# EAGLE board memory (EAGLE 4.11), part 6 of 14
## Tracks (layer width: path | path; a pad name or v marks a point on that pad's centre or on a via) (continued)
-S  (via drill 0.61) (continued)
  Bottom 0.254: A23.H2 220.98,391.16 223.52,391.16 224.79,392.43 227.33,392.43 227.97,391.8 236.85,391.8 237.49,392.43 244.47,392.43 245.75,391.16 A21.H2 246.38,391.16 248.92,391.16 250.19,392.43 256.54,392.43 259.71,395.61 262.25,395.61 266.06,391.8 274.95,391.8 278.76,395.61 287.65,395.61 288.29,394.97 295.27,394.97 v295.27,393.7 | B40.K2 4.45,314.96 2.54,316.87 1.91,316.87 B40.J2 | 159.38,342.27 v158.75,342.9 | 159.38,342.27 219.07,342.27 v219.71,342.9 | v18.41,325.75 13.97,325.75 10.16,321.95 3.17,321.95 1.91,323.22 B40.F2 | v19.05,349.89 19.05,353.06 138.43,353.06 v139.06,352.43 | v141.6,342.9 142.24,342.27 159.38,342.27
-SA1  (via drill 0.61)
  Top 0.254: v347.35,285.12 346.71,284.48 v346.71,278.77 | v27.3,314.33 28.57,315.6 28.57,344.81 27.3,346.08 27.3,354.97 A38.V2
  Route2 0.254: v347.35,285.12 348.62,283.85 363.86,283.85 364.49,284.48 368.94,284.48 370.2,283.21 380.37,283.21 382.27,285.12 B10.V2 | v346.71,278.77 345.44,280.04 337.82,280.04 336.55,281.31 335.92,281.31 332.74,278.13 315.6,278.13 310.51,283.21 290.83,283.21 288.93,281.31 268.61,281.31 262.25,287.66 255.91,287.66 v245.75,297.81 | v175.9,306.07 172.09,309.88 161.29,309.88 160.66,309.25 151.76,309.25 147.96,313.06 142.24,313.06 141.6,312.42 135.89,312.42 132.08,316.23 125.09,316.23 121.28,312.42 110.49,312.42 106.68,316.23 97.79,316.23 97.16,315.6 94.61,315.6 91.44,318.77 85.09,318.77 84.45,319.41 75.56,319.41 68.58,312.42 59.69,312.42 59.05,313.06 51.44,313.06 46.35,307.98 45.09,307.98 40.64,312.42 34.29,312.42 33.66,313.06 28.57,313.06 v27.3,314.33
  Route3 0.254: v245.75,297.81 243.21,300.36 v243.21,300.99
  Bottom 0.254: A38.V2 27.3,356.24 29.21,358.14 29.84,358.14 A38.U2 | v243.21,300.99 245.75,303.53 245.75,306.07 237.49,306.07 236.85,306.71 227.97,306.71 227.33,306.07 224.79,306.07 224.16,306.71 215.26,306.71 214.63,306.07 212.09,306.07 211.46,306.71 202.56,306.71 201.93,306.07 199.39,306.07 198.75,306.71 189.87,306.71 189.23,306.07 186.69,306.07 186.06,306.71 177.16,306.71 176.53,306.07 v175.9,306.07
-SAC  (via drill 0.61)
  Top 0.254: 260.35,393.06 255.91,393.06 A20.F2 | 260.35,393.06 260.35,379.73 259.08,378.46 A20.M2 | v264.8,400.05 260.35,395.61 260.35,393.06
  Route2 0.254: v426.72,419.1 425.45,417.83 306.7,417.83 v304.8,415.93
  Route3 0.254: v503.56,261.62 504.82,262.89 504.82,363.22 448.94,419.1 v426.72,419.1 | v280.67,415.93 v264.8,400.05
  Bottom 0.254: v503.56,261.62 501.01,259.08 500.38,259.08 500.38,255.91 504.82,251.46 504.82,186.69 497.84,179.7 497.2,179.7 497.2,175.26 D01.L2 | v304.8,415.93 304.17,416.56 281.31,416.56 v280.67,415.93
-SAC00  (via drill 0.61)
  Top 0.254: v411.48,73.66 411.48,85.09 E08.U2 | v501.65,109.22 501.65,115.57 500.38,116.84 E01.H2
  Bottom 0.254: v411.48,73.66 412.12,73.02 475.62,73.02 476.25,72.39 494.67,72.39 | 494.67,72.39 497.84,69.22 497.84,64.77 494.03,64.77 485.14,55.88 480.06,55.88 473.71,49.53 466.09,49.53 465.45,48.9 464.19,48.9 462.92,50.16 459.11,50.16 F04.F2 | v501.65,109.22 501.65,72.39 494.67,72.39
-SAC01  (via drill 0.61)
  Top 0.254: v493.39,32.38 498.48,37.46 498.48,69.22 | 498.48,69.22 498.48,121.92 499.75,123.19 E01.E2 | v413.38,70.48 410.21,73.66 410.21,81.28 407.04,81.28 406.4,81.91 406.4,83.18 407.04,83.82 407.04,87.63 407.67,88.27 E08.T2 | 498.48,69.22 v496.57,69.22
  Bottom 0.254: v493.39,32.38 490.86,29.84 490.22,29.84 489.58,30.48 480.69,30.48 474.35,24.13 468,24.13 467.36,23.49 460.38,23.49 459.11,24.77 F04.R2 | v413.38,70.48 422.27,70.48 422.91,71.12 487.05,71.12 488.95,69.22 v496.57,69.22
-SAC02  (via drill 0.61)
  Top 0.254: v442.6,93.98 444.5,95.88 444.5,108.58 v446.4,110.49 | v459.11,147.32 458.47,146.69 458.47,135.25 457.2,133.99 457.2,122.55 458.47,121.28 E04.F2
  Bottom 0.254: v442.6,93.98 441.96,93.34 439.42,93.34 438.79,93.98 429.89,93.98 429.26,93.34 426.72,93.34 426.08,93.98 417.19,93.98 416.56,93.34 412.12,93.34 411.48,92.71 E08.S2 | v446.4,110.49 455.93,120.02 458.47,120.02 E04.F2 | v459.11,147.32 499.75,147.32 499.75,151.76 D01.U2
-SAC03
  Route2 0.254: D01.P2 499.75,164.47 499.75,160.02 499.11,160.02 495.3,156.21 495.3,138.43 493.39,138.43 460.38,105.41 460.38,95.88 459.11,95.88 E04.R2
  Bottom 0.254: E08.R2 408.31,95.25 412.12,95.25 414.02,97.16 416.56,97.16 417.19,96.52 426.08,96.52 426.72,97.16 429.26,97.16 429.89,96.52 438.79,96.52 442.6,100.33 451.49,100.33 455.93,95.88 458.47,95.88 E04.R2
-SAC04  (via drill 0.61)
  Top 0.254: v415.93,98.42 415.93,126.36 419.1,129.54 v419.1,145.41 | v441.32,145.41 v441.32,186.06
  Route2 0.254: v494.03,187.32 495.3,186.06 496.57,186.06 496.57,181.61 D01.J2
  Bottom 0.254: v415.93,98.42 411.48,98.42 E08.P2 | v419.1,145.41 v441.32,145.41 | v441.32,186.06 450.21,186.06 450.85,185.42 454.66,185.42 455.93,186.69 458.47,186.69 D04.F2 459.11,187.96 460.38,189.23 465.45,189.23 466.09,188.59 468.63,188.59 469.26,189.23 478.15,189.23 478.79,188.59 481.33,188.59 481.96,189.23 492.12,189.23 v494.03,187.32
-SAC05  (via drill 0.61)
  Top 0.254: v406.4,140.34 406.4,107.31 407.04,106.68 407.04,102.87 407.67,102.23 E08.N2 | v457.2,141.6 457.2,160.02 458.47,161.29 D04.R2 | v499.75,168.91 501.65,170.81 501.65,184.78 500.38,186.06 500.38,189.86 D01.E2
  Bottom 0.254: v406.4,140.34 407.04,140.97 410.85,140.97 411.48,140.34 427.36,140.34 428.62,141.6 v457.2,141.6 | v499.75,168.91 487.68,156.84 480.06,156.84 476.88,160.02 469.26,160.02 465.45,163.83 460.38,163.83 459.11,162.56 D04.R2
-SAC06  (via drill 0.61)
  Top 0.254: v487.68,140.34 487.68,150.5 488.95,151.76 488.95,204.47 493.39,208.91 v493.39,217.17 | v477.52,254 479.43,252.09 v479.43,224.79
  Route2 0.254: v477.52,128.91 487.68,139.06 v487.68,140.34
  Bottom 0.254: v477.52,128.91 474.35,125.73 468,125.73 466.09,123.82 465.45,123.82 463.55,125.73 455.3,125.73 448.31,118.74 444.5,118.74 438.15,125.09 434.34,125.09 427.99,118.74 422.91,118.74 414.02,109.85 411.48,109.85 411.48,105.41 E08.M2 | v493.39,217.17 493.39,220.34 | 493.39,220.34 495.3,220.34 497.2,222.25 499.75,222.25 C01.U2 | v477.52,254 475.62,255.91 468,255.91 467.36,255.27 460.38,255.27 459.11,256.54 C04.F2 | v479.43,224.79 480.06,224.16 485.14,224.16 485.77,223.52 490.22,223.52 493.39,220.34
-SAC07  (via drill 0.61)
  Top 0.254: v409.57,139.7 409.57,119.38 410.85,118.11 E08.H2 | v428.62,140.34 428.62,179.7 431.8,182.88 v431.8,203.2 | v454.02,204.47 v454.02,231.14
  Bottom 0.254: v409.57,139.7 427.99,139.7 v428.62,140.34 | v431.8,203.2 433.07,204.47 441.96,204.47 442.6,205.1 453.39,205.1 v454.02,204.47 | v454.02,231.14 458.47,231.14 C04.R2 459.11,231.78 461.01,231.78 462.92,233.68 465.45,233.68 469.26,229.87 478.15,229.87 478.79,230.5 481.33,230.5 481.96,229.87 490.86,229.87 491.49,230.5 498.48,230.5 499.75,229.23 C01.S2
-SAC08  (via drill 0.61)
  Top 0.254: v452.12,123.82 454.02,125.73 454.02,135.89 v452.75,137.16 | v497.84,137.79 498.48,138.43 498.48,236.22 | 498.48,236.22 497.2,237.49 C01.N2 | v486.41,312.42 488.95,309.88 488.95,302.26 498.48,292.74 498.48,236.22
  Route2 0.254: v471.81,321.31 480.69,312.42 v486.41,312.42
  Bottom 0.254: v452.12,123.82 447.68,119.38 445.13,119.38 438.79,125.73 428.62,125.73 415.29,112.39 412.12,112.39 411.48,111.76 E08.K2 | v452.75,137.16 455.3,139.7 455.93,139.06 486.41,139.06 487.05,138.43 497.2,138.43 v497.84,137.79 | v471.81,321.31 471.17,321.31 469.26,323.22 467.36,323.22 466.09,321.95 460.38,321.95 459.11,323.22 B04.F2
-SAC09  (via drill 0.61)
  Top 0.254: v492.12,141.6 492.12,206.38 494.67,208.91 494.67,220.98 495.3,221.61 495.3,245.75 496.57,247.01 496.57,250.19 C01.J2 | v486.41,299.72 492.12,294 v492.12,252.09
  Route3 0.254: v411.48,141.6 411.48,140.34 409.57,138.43 409.57,122.55 408.31,121.28 E08.F2
  Bottom 0.254: v411.48,141.6 427.36,141.6 427.99,142.24 456.56,142.24 457.2,142.88 459.11,140.97 487.05,140.97 487.68,141.6 v492.12,141.6 | v486.41,299.72 480.69,299.72 480.06,300.36 477.52,300.36 476.88,299.72 468,299.72 467.36,300.36 464.82,300.36 464.19,299.72 459.74,299.72 459.11,299.09 B04.R2 | v492.12,252.09 492.76,251.46 496.57,251.46 C01.J2
-SAC10  (via drill 0.61)
  Top 0.254: v490.86,241.3 494.67,245.11 494.67,246.38 495.3,247.01 495.3,252.09 496.57,253.36 v496.57,254.63 | v492.76,361.95 504.82,349.89 504.82,297.81 502.29,295.28 502.29,293.37 501.65,292.74 v501.65,281.31
  Route2 0.254: v492.76,361.95 465.45,389.25 459.11,389.25 459.11,393.06 A04.F2
  Route3 0.254: v421,212.72 419.1,210.82 419.1,183.51 415.93,180.34 415.93,143.51 412.75,140.34 412.75,125.73 411.48,124.46 E08.E2 | v490.86,220.98 492.12,222.25 492.12,240.03 v490.86,241.3
  Bottom 0.254: v421,212.72 422.27,214 447.04,214 447.68,213.36 450.85,213.36 452.12,214.63 476.25,214.63 479.43,217.81 480.69,217.81 483.87,220.98 v490.86,220.98 | v496.57,254.63 499.75,257.81 499.75,259.72 C01.E2 500.38,260.99 501.65,260.99 501.65,270.51 502.92,271.78 502.92,277.5 501.65,278.77 v501.65,281.31
-SAC11  (via drill 0.61)
  Top 0.254: v408.31,131.44 408.31,127.63 E08.D2 | v499.75,139.06 501.65,140.97 501.65,169.54 504.82,172.72 504.82,276.86 500.38,281.31 500.38,288.29 B01.U2 500.38,289.56 500.38,292.74 501.65,294 501.65,348.62 v490.22,360.05
  Route2 0.254: v408.31,131.44 418.46,141.6 428.62,141.6 v429.89,140.34 | v490.22,360.05 483.87,360.05 476.88,367.03 468,367.03 467.36,366.4 460.38,366.4 459.11,367.67 A04.R2
  Bottom 0.254: v429.89,140.34 431.17,139.06 436.88,139.06 438.15,140.34 455.93,140.34 456.56,139.7 487.05,139.7 487.68,139.06 v499.75,139.06
-SIK  (via drill 0.61)
  Top 0.254: v275.59,409.58 282.57,416.56 300.99,416.56 300.99,414.02 v306.7,408.31 | v312.42,410.21 314.32,412.12 314.32,419.74 316.23,421.64 495.3,421.64 495.3,395.61 496.57,394.34 A01.F2
  Route2 0.254: v122.56,390.53 127.64,395.61 137.16,395.61 140.97,391.8 149.86,391.8 153.67,395.61 162.56,395.61 163.19,394.97 172.09,394.97 175.9,398.78 180.34,398.78 180.97,398.15 186.69,398.15 193.04,404.5 200.66,404.5 208.28,412.12 246.38,412.12 254,404.5 264.16,404.5 267.97,408.31 274.32,408.31 v275.59,409.58 | v306.7,408.31 310.51,408.31 v312.42,410.21
  Route3 0.254: v90.17,307.98 85.72,312.42 85.72,346.71 95.25,356.24 95.25,368.94 115.57,389.25 122.56,389.25 v122.56,390.53
  Bottom 0.254: v90.17,307.98 93.34,307.98 B33.M2
-SL  (via drill 0.61)
  Top 0.254: v481.33,270.51 478.79,273.05 478.79,284.48 479.43,285.12 v479.43,292.1 | v494.03,298.45 498.48,302.9 v498.48,350.52
  Route2 0.254: v485.77,255.27 485.77,268.61 483.24,268.61 v481.33,270.51 | v498.48,350.52 498.48,357.5 501.01,357.5 501.65,358.14 501.65,369.57 492.76,369.57 447.04,415.29 439.42,415.29 438.79,415.93 412.75,415.93 411.48,417.2 396.24,417.2 394.33,415.29 367.03,415.29 365.12,417.2 321.94,417.2 v320.68,415.93 | v262.89,417.2 258.44,412.75 207.01,412.75 201.93,407.67 199.39,407.67 198.75,408.31 189.87,408.31 v180.97,399.42
  Route3 0.254: v440.06,77.47 434.98,72.39 434.98,59.05 433.7,57.79 F06.D2 | v483.87,99.69 482.6,100.96 482.6,120.02 479.43,123.19 479.43,160.02 482.6,163.19 482.6,176.53 483.87,177.8 483.87,178.44 482.6,179.7 482.6,214.63 485.77,217.81 485.77,223.52 487.05,224.79 487.05,226.69 485.77,227.97 v485.77,255.27 | v320.68,415.93 316.87,415.93 314.96,417.83 274.32,417.83 274.32,417.2 273.05,415.93 270.51,415.93 269.24,417.2 v262.89,417.2 | v180.97,399.42 166.37,384.81 v166.37,384.18
  Bottom 0.254: v440.06,77.47 440.69,78.1 475.62,78.1 485.77,88.27 485.77,99.69 v483.87,99.69 | v479.43,292.1 480.69,293.37 488.95,293.37 v494.03,298.45 | v166.37,384.18 164.47,386.08 161.29,386.08 160.02,384.81 157.48,384.81 A28.K2
-SP  (via drill 0.61)
  Top 0.254: v31.75,254 v31.75,321.95 31.75,375.92 v33.66,377.83 | v393.7,317.5 393.7,300.36 394.97,299.09 B09.R2 | v357.5,319.41 357.5,323.22 B12.F2 | v401.95,135.25 400.69,136.53 400.69,139.7 401.32,140.34 401.32,146.69 403.23,148.59 403.23,170.18 v401.95,171.45
  Route2 0.254: v404.5,101.6 406.4,103.5 406.4,121.92 404.5,121.92 403.23,123.19 403.23,135.25 v401.95,135.25 | v404.5,226.69 403.23,227.97 403.23,241.3 v401.95,241.3 | v74.93,323.85 76.83,321.95 86.36,321.95 87,322.58 89.53,322.58 92.71,319.41 99.06,319.41 99.69,318.77 108.58,318.77 112.39,322.58 121.28,322.58 125.09,318.77 133.99,318.77 134.62,319.41 137.16,319.41 140.97,315.6 147.96,315.6 151.76,319.41 162.56,319.41 163.19,318.77 172.09,318.77 175.9,322.58 176.53,322.58 179.71,319.41 187.96,319.41 188.59,318.77 197.49,318.77 198.12,319.41 200.66,319.41 201.29,318.77 210.19,318.77 217.17,325.75 226.06,325.75 229.87,321.95 238.76,321.95 242.57,325.75 250.19,325.75 254,321.95 262.89,321.95 v264.8,323.85
  Route3 0.254: v273.05,321.31 273.05,303.53 271.78,302.26 B19.P2 | v401.95,171.45 400.69,172.72 400.69,173.35 400.05,173.99 400.05,182.88 404.5,187.32 403.23,188.59 403.23,191.13 v404.5,192.41 | v408.31,195.58 407.04,196.85 407.04,198.75 406.4,199.39 406.4,224.79 v404.5,226.69 | v401.95,241.3 400.05,243.2 400.05,291.47 395.61,295.91 395.61,297.81 B09.R2
  Bottom 0.254: v31.75,254 32.38,254 34.29,252.09 38.73,252.09 39.37,251.46 C37.J2 | v33.66,377.83 39.37,383.54 42.55,383.54 A37.K2 | E12.R2 357.5,94.61 358.77,93.34 363.86,93.34 365.12,94.61 369.57,94.61 E11.R2 370.2,95.88 371.48,97.16 378.46,97.16 381.63,93.98 385.44,93.98 391.8,100.33 394.33,100.33 397.51,97.16 400.05,97.16 v404.5,101.6 | 273.69,321.95 v273.05,321.31 | 273.69,321.95 276.86,321.95 277.5,322.58 278.76,322.58 279.4,321.95 289.56,321.95 290.19,322.58 295.91,322.58 296.55,321.95 302.26,321.95 302.89,322.58 311.79,322.58 312.42,321.95 314.96,321.95 315.6,322.58 316.87,322.58 317.5,321.95 327.66,321.95 328.3,322.58 334.01,322.58 334.64,321.95 340.36,321.95 341,322.58 349.88,322.58 350.52,321.95 351.79,321.95 353.06,323.22 356.87,323.22 B12.F2 | v393.7,317.5 392.43,318.77 389.89,318.77 389.25,319.41 380.37,319.41 379.73,318.77 377.19,318.77 376.56,319.41 372.11,319.41 371.48,318.77 364.49,318.77 363.86,319.41 v357.5,319.41 | v404.5,192.41 408.94,192.41 409.57,193.04 409.57,195.58 v408.31,195.58 | v31.75,321.95 35.56,321.95 36.2,322.58 45.09,322.58 45.72,321.95 48.26,321.95 52.07,325.75 60.96,325.75 61.59,325.12 70.48,325.12 71.12,325.75 73.03,325.75 v74.93,323.85 | v264.8,323.85 265.43,323.22 266.7,323.22 267.97,321.95 273.69,321.95
-SSK  (via drill 0.61)
  Top 0.254: v411.48,415.93 408.31,419.1 314.96,419.1 314.96,411.48 v313.69,410.21
  Route2 0.254: v445.13,410.85 441.32,414.66 438.79,414.66 438.15,415.29 412.12,415.29 v411.48,415.93 | v313.69,410.21 308.61,405.13 303.53,405.13 297.81,410.85 291.46,410.85 287.65,414.66 274.95,414.66 v274.32,415.29
  Route3 0.254: B36.N2 52.7,305.44 52.7,309.25 55.24,311.79 55.24,313.69 B36.K2 | B34.P2 80.64,302.26 v80.64,306.07 79.38,307.34 79.38,311.79 76.2,314.96 76.2,351.16 123.19,398.15 123.19,398.78 132.08,398.78 135.89,394.97 144.78,394.97 158.75,408.94 158.75,412.75 166.37,412.75 167.64,411.48 200.66,411.48 201.29,412.12 233.04,412.12 240.66,404.5 250.82,404.5 255.27,408.94 255.27,411.48 267.33,411.48 271.14,415.29 v274.32,415.29
  Bottom 0.254: v80.64,306.07 72.39,306.07 71.75,306.71 64.14,306.71 63.5,306.07 59.69,306.07 59.05,306.71 55.88,306.71 53.98,304.8 52.7,304.8 B36.N2 | v445.13,410.85 445.77,411.48 474.98,411.48 484.5,401.96 488.95,401.96 488.95,393.06 495.94,386.08 496.57,386.08 496.57,381.64 A01.L2
-STOS  (via drill 0.61)
  Top 0.254: v266.7,399.42 255.27,410.85 255.27,417.2 254,418.47 194.94,418.47 v194.94,415.29 | v5.71,412.75 3.17,410.21 3.17,392.43 4.45,391.16 A40.H2
  Route2 0.254: v266.7,399.42 267.97,398.15 274.95,398.15 278.76,401.96 287.65,401.96 291.46,398.15 300.36,398.15 300.99,398.78 303.53,398.78 304.17,398.15 313.06,398.15 316.23,401.32 322.58,401.32 326.39,405.13 332.74,405.13 340.36,412.75 441.96,412.75 446.4,408.31 452.75,408.31 492.76,368.3 496.57,368.3 A01.R2
  Route3 0.254: v194.94,415.29 189.23,421 v171.45,421
  Bottom 0.254: v171.45,421 170.81,421.64 14.61,421.64 v5.71,412.75
-STROBE  (via drill 0.61)
  Top 0.254: v55.24,180.97 55.24,183.51 D36.H2 | v74.3,186.06 76.2,187.96 v76.2,210.19 | v179.71,208.28 179.71,218.44 C26.V2
  Bottom 0.254: v55.24,180.97 52.7,180.97 D36.J2 | C26.V2 179.71,219.07 183.51,219.07 188.59,224.16 189.23,224.16 192.41,220.98 200.66,220.98 201.29,220.34 210.19,220.34 210.82,220.98 213.36,220.98 214.63,219.71 217.17,219.71 C23.V2 | v74.3,186.06 73.66,185.42 71.12,185.42 70.48,186.06 61.59,186.06 60.96,185.42 56.52,185.42 55.88,184.78 D36.H2 | v76.2,210.19 77.47,211.45 114.94,211.45 115.57,210.82 132.72,210.82 133.99,212.09 144.78,212.09 148.59,208.28 v179.71,208.28
-STS  (via drill 0.61)
  Top 0.254: v303.53,343.54 301.62,343.54 301.62,344.17 300.99,344.81 300.99,354.33 301.62,354.97 301.62,356.24 v299.72,358.14
  Route2 0.254: v287.02,86.99 v287.02,84.45 | v243.21,104.14 v252.73,94.61 | v303.53,343.54 304.8,343.54 308.61,347.35 368.3,347.35 369.57,346.08 402.59,346.08 406.4,342.27 436.25,342.27 440.69,337.82 447.04,337.82 453.39,331.47 460.38,331.47 483.87,307.98 485.14,307.98 493.39,299.72 495.94,299.72 496.57,299.09 B01.R2 | v299.72,358.14 298.45,356.87 289.56,356.87 288.29,358.14 285.75,358.14 284.48,356.87 280.04,356.87 272.42,349.25 266.7,349.25 264.8,347.35 262.89,347.35 v261.62,348.62
  Route3 0.254: v287.02,84.45 285.75,83.18 285.75,81.28 291.46,75.56 291.46,71.75 294,71.75 304.8,60.96 304.8,46.36 306.07,45.09 F16.J2 | v223.52,117.47 222.25,118.74 222.25,142.88 219.71,145.41 219.71,149.22 219.07,149.86 219.07,199.39 222.25,202.56 222.25,212.72 225.43,215.9 225.43,229.23 228.6,232.41 228.6,238.76 237.49,247.65 235.59,249.56 232.41,249.56 232.41,250.82 234.95,253.36 234.95,280.04 233.68,281.31 233.68,287.02 234.95,288.29 234.95,346.71 238.76,350.52 238.76,354.33 v245.75,361.31 | v261.62,348.62 260.35,349.89 260.35,363.22 259.08,364.49 A20.S2
  Bottom 0.254: v287.02,86.99 286.38,87.63 279.4,87.63 276.23,90.8 266.06,90.8 265.43,90.17 262.89,90.17 259.08,93.98 253.37,93.98 v252.73,94.61 | v243.21,104.14 237.49,109.85 231.14,109.85 v223.52,117.47 | v245.75,361.31 248.28,363.86 251.46,363.86 252.09,363.22 254,363.22 255.91,365.12 258.44,365.12 A20.S2
-SX  (via drill 0.61)
  Top 0.254: B25.K2 194.94,313.69 193.68,312.42 193.68,306.71 192.41,305.44 B25.N2 192.41,304.17 192.41,302.26 194.31,300.36 194.31,296.55 194.94,295.91 B25.S2 | v211.46,370.84 209.55,372.75 209.55,388.62 208.28,389.89 A24.H2 208.28,391.16 208.28,394.34 v215.9,401.96 | v219.07,327.03 219.07,342.27 218.44,342.9 218.44,354.33 219.07,354.97 219.07,362.59 217.81,363.86 217.81,367.67 A23.R2
  Route3 0.254: v196.85,320.68 196.85,316.23 195.58,314.96 B25.K2
  Bottom 0.254: v211.46,370.84 213.36,368.94 217.17,368.94 A23.R2 | v215.9,401.96 224.16,401.96 224.79,401.32 227.33,401.32 227.97,401.96 236.85,401.96 238.76,400.05 242.57,400.05 A21.D2 | v196.85,320.68 197.49,321.31 200.03,321.31 203.84,325.12 210.19,325.12 210.82,325.75 213.36,325.75 214,325.12 217.17,325.12 v219.07,327.03
-SY  (via drill 0.61)
  Top 0.254: B23.J2 217.81,316.87 218.44,316.23 218.44,314.33 219.71,313.06 221.62,313.06 222.25,313.69 222.25,318.77 220.98,320.04 B23.H2 220.98,321.31 222.25,322.58 v222.25,356.87 222.25,394.97 220.98,396.24 A23.E2 | 193.68,354.97 194.94,356.24 194.94,358.14 A25.U2 | 193.68,354.97 192.41,353.7 192.41,338.46 193.68,337.19 193.68,325.75 192.41,324.49 B25.F2 | 193.68,354.97 193.68,368.94 193.04,369.57 193.04,373.38 192.41,374.02 A25.N2 | A27.K2 169.54,383.54 169.54,381.64 167,379.1 167,375.29 A27.N2 166.37,374.02 v166.37,371.48
  Route2 0.254: v166.37,371.48 164.47,373.38 163.19,373.38 159.38,369.57 150.5,369.57 149.86,370.21 143.51,370.21 140.34,373.38 137.16,373.38 133.35,369.57 125.09,369.57 121.28,373.38 112.39,373.38 111.76,372.75 100.97,372.75 84.45,389.25 81.92,389.25 81.28,389.89 A34.H2
  Route3 0.254: A27.S2 169.54,365.76 168.28,367.03 168.28,372.75 167,374.02 A27.N2
  Bottom 0.254: A23.E2 220.98,396.24 221.62,395.61 226.06,395.61 226.69,394.97 235.59,394.97 236.22,395.61 238.76,395.61 239.4,394.97 244.47,394.97 245.75,396.24 A21.E2 | A25.U2 195.58,358.14 198.12,358.14 199.39,356.87 206.38,356.87 207.65,358.14 A24.U2 208.28,358.78 210.82,358.78 212.72,356.87 v222.25,356.87 | A25.N2 191.77,375.29 187.32,375.29 186.06,376.56 177.16,376.56 176.53,375.92 173.99,375.92 173.35,376.56 170.18,376.56 168.28,374.65 167,374.65 A27.N2
-T0  (via drill 0.61)
  Top 0.254: v127,371.48 127,357.5 128.27,356.24 A30.V2 | v142.88,373.38 142.88,388.62 144.15,389.89 A29.H2
  Bottom 0.254: v127,371.48 128.27,372.75 137.16,372.75 137.79,373.38 v142.88,373.38 | A26.H2 182.25,391.16 180.97,392.43 173.99,392.43 173.35,391.8 164.47,391.8 163.83,392.43 161.29,392.43 160.66,391.8 151.76,391.8 151.13,392.43 148.59,392.43 147.32,391.16 144.78,391.16 A29.H2
-T1  (via drill 0.61)
  Top 0.254: A30.S2 132.08,365.76 133.35,367.03 v133.35,380.37 133.35,396.24 135.89,398.78 v137.16,398.78
  Bottom 0.254: v133.35,380.37 128.91,380.37 A30.L2 | v137.16,398.78 138.43,398.78 139.06,398.15 147.96,398.15 151.76,401.96 160.66,401.96 161.29,401.32 163.83,401.32 164.47,401.96 173.35,401.96 173.99,401.32 178.44,401.32 179.07,400.69 A26.D2
-T2
  Route3 0.254: A31.V2 116.2,356.24 117.47,357.5 117.47,367.67 130.18,380.37 130.18,388.62 131.44,389.89 A30.H2
-T3  (via drill 0.61)
  Top 0.254: v94.61,52.7 95.25,53.34 95.25,338.46 v99.69,342.9 | v112.39,342.9 120.65,351.16 120.65,363.22 | 120.65,363.22 119.38,364.49 A31.S2 | 120.65,363.22 120.65,391.8 118.11,391.8 117.47,391.16 117.47,386.72 116.84,386.08 116.84,382.27 116.2,381.64 A31.L2
  Bottom 0.254: v94.61,52.7 90.17,52.7 86.36,48.9 77.47,48.9 73.66,52.7 71.12,52.7 70.48,52.07 61.59,52.07 60.96,52.7 56.52,52.7 55.88,53.34 F36.E2 | v99.69,342.9 v112.39,342.9
-T4  (via drill 0.61)
  Top 0.254: v104.78,382.27 104.78,380.37 104.14,379.73 104.14,378.46 101.6,375.92 101.6,357.5 102.87,356.24 A32.V2 | v161.93,397.51 161.93,399.42 166.37,399.42 A27.D2 | v180.97,380.37 180.97,373.38 182.25,372.11 A26.P2
  Bottom 0.254: v104.78,382.27 104.78,385.45 110.49,385.45 114.94,389.89 118.75,389.89 A31.H2 119.38,389.89 121.92,389.89 123.19,388.62 125.73,388.62 126.36,389.25 135.25,389.25 135.89,388.62 139.7,388.62 140.34,389.25 | v161.93,397.51 159.38,394.97 148.59,394.97 147.96,395.61 146.69,395.61 140.34,389.25 | v180.97,380.37 180.97,382.27 175.26,382.27 172.72,384.81 171.45,384.81 170.81,385.45 166.37,385.45 162.56,389.25 151.76,389.25 151.13,388.62 148.59,388.62 147.96,389.25 140.34,389.25
-T5
  Top 0.254: A32.S2 106.68,365.76 107.95,367.03 107.95,384.81 107.31,385.45 103.5,385.45 103.5,381.64 A32.L2
  Bottom 0.254: A26.L2 179.07,381.64 174.62,381.64 173.35,382.91 164.47,382.91 163.83,382.27 161.29,382.27 160.66,382.91 151.76,382.91 147.96,379.1 145.41,379.1 142.24,382.27 135.89,382.27 135.25,382.91 126.36,382.91 125.73,382.27 123.19,382.27 122.56,382.91 113.67,382.91 113.03,382.27 110.49,382.27 109.86,382.91 106.68,382.91 104.78,381 103.5,381 A32.L2
-T6
  Top 0.254: A26.J2 179.71,387.99 180.34,388.62 180.34,392.43 182.25,394.34 182.25,396.24 A26.E2
  Bottom 0.254: A32.H2 106.68,391.16 107.31,391.8 111.76,391.8 112.39,392.43 121.28,392.43 121.92,391.8 124.46,391.8 125.09,392.43 133.99,392.43 134.62,391.8 137.16,391.8 137.79,392.43 142.24,392.43 144.15,394.34 144.15,396.24 A29.E2 144.78,397.51 148.59,397.51 149.86,398.78 151.13,398.78 151.76,398.15 160.66,398.15 161.29,398.78 163.83,398.78 164.47,398.15 173.35,398.15 173.99,398.78 176.53,398.78 177.16,398.15 181.61,398.15 182.25,397.51 A26.E2
-TAD  (via drill 0.61)
  Top 0.254: v320.68,34.29 320.68,31.12 320.04,30.48 320.04,29.84 320.68,29.21 320.68,24.13 321.94,22.86 F15.S2 | v403.23,50.8 403.23,67.94 396.88,74.29 v396.88,85.09 | v311.15,74.29 v311.15,37.46 | v336.55,98.42 v336.55,75.56 | v269.88,260.99 v269.88,310.52
  Route2 0.254: v320.68,34.29 318.13,36.83 313.69,36.83 313.06,36.2 311.15,36.2 | 311.15,36.2 307.98,36.2 306.7,37.46 F16.L2 | v295.27,144.14 296.55,142.88 297.81,142.88 299.72,144.78 315.6,144.78 317.5,142.88 v344.17,142.88 | v396.88,85.09 386.08,95.88 386.08,97.79 E10.P2 | v311.15,37.46 311.15,36.2 | v287.65,177.8 287.65,176.53 293.37,170.81 293.37,168.91 D17.N2
  Route3 0.254: v295.27,144.14 295.27,166.37 294,167.64 D17.N2 | v344.17,142.88 346.07,140.97 346.07,133.99 349.25,130.81 349.25,106.04 v351.79,103.5 | v282.57,256.54 282.57,210.82 281.31,209.55 281.31,201.93 282.57,200.66 282.57,189.23 287.65,184.15 287.65,182.88 288.93,181.61 288.93,179.07 v287.65,177.8
  Bottom 0.254: 269.88,312.42 273.69,312.42 274.32,313.06 276.86,313.06 277.5,312.42 286.38,312.42 287.02,313.06 289.56,313.06 290.19,312.42 299.08,312.42 299.72,313.06 302.26,313.06 302.89,312.42 311.79,312.42 312.42,313.06 314.96,313.06 315.6,312.42 324.49,312.42 325.12,313.06 327.66,313.06 328.3,312.42 337.19,312.42 337.82,313.06 339.09,313.06 340.36,311.79 344.17,311.79 B13.L2 | 269.88,312.42 264.8,312.42 264.16,313.06 261.62,313.06 259.71,311.15 255.91,311.15 B20.L2 | F20.H2 259.08,46.99 259.71,46.36 264.16,46.36 267.97,42.55 276.86,42.55 277.5,43.18 280.04,43.18 287.02,36.2 289.56,36.2 290.19,36.83 299.08,36.83 299.72,36.2 301.62,36.2 303.53,38.1 306.07,38.1 F16.L2 | 353.69,101.6 355.6,99.69 365.76,99.69 366.39,100.33 375.29,100.33 375.92,99.69 378.46,99.69 379.1,100.33 384.18,100.33 385.44,99.06 E10.P2 | v351.79,103.5 353.69,101.6 | v403.23,50.8 404.5,49.53 408.94,49.53 410.85,51.44 412.12,51.44 413.38,52.7 414.65,52.7 415.29,52.07 417.83,52.07 418.46,52.7 427.36,52.7 430.53,49.53 433.07,49.53 433.07,45.09 F06.J2 | v311.15,74.29 311.79,74.93 314.96,74.93 315.6,75.56 v336.55,75.56 | v336.55,98.42 337.82,99.69 340.36,99.69 341,100.33 349.88,100.33 350.52,99.69 351.79,99.69 353.69,101.6 | v269.88,310.52 269.88,312.42 | v269.88,260.99 269.88,259.08 276.86,259.08 280.04,255.91 281.94,255.91 v282.57,256.54
-TP  (via drill 0.61)
  Top 0.254: v20.95,240.66 19.05,242.57 19.05,258.44 17.78,259.72 C39.E2 | v255.91,308.61 254,310.52 254,366.4 255.27,367.67 A20.R2 | v267.97,300.99 267.97,299.09 B19.R2 | v127,262.89 128.27,261.62 136.53,261.62 136.53,259.72 v140.97,255.27
  Route2 0.254: v168.91,262.25 175.26,268.61 184.78,268.61 188.59,264.8 197.49,264.8 201.29,268.61 210.19,268.61 210.82,267.97 213.36,267.97 214,268.61 222.88,268.61 223.52,267.97 226.06,267.97 226.69,268.61 235.59,268.61 236.22,267.97 238.76,267.97 241.94,271.15 v246.38,271.15
  Route3 0.254: v246.38,271.15 247.65,272.42 247.65,300.36 v248.92,301.62
  Bottom 0.254: C39.F2 14.61,257.81 16.51,259.72 17.14,259.72 C39.E2 17.78,260.99 18.41,261.62 22.86,261.62 23.5,262.25 32.38,262.25 33.02,261.62 35.56,261.62 39.37,265.43 48.26,265.43 52.07,261.62 60.96,261.62 61.59,262.25 70.48,262.25 71.12,261.62 73.66,261.62 77.47,265.43 86.36,265.43 90.17,261.62 99.06,261.62 99.69,262.25 108.58,262.25 109.22,261.62 111.76,261.62 113.03,262.89 114.3,262.89 114.94,262.25 118.75,262.25 121.92,265.43 123.19,265.43 125.73,262.89 v127,262.89 | v20.95,240.66 25.4,236.22 31.11,236.22 34.29,233.04 38.73,233.04 39.37,232.41 C37.R2 | B19.R2 268.61,299.09 273.05,299.09 274.32,300.36 275.59,300.36 276.86,299.09 280.67,299.09 B18.R2 | v267.97,300.99 262.25,306.71 257.81,306.71 v255.91,308.61 v248.92,301.62 | v140.97,255.27 148.59,255.27 154.94,261.62 162.56,261.62 163.19,262.25 v168.91,262.25
-TSH  (via drill 0.61)
  Top 0.254: 219.07,103.5 217.81,102.23 E23.N2 | 219.07,103.5 219.07,106.04 220.34,107.31 220.34,110.49 E23.K2 | 219.07,103.5 219.07,87.63 220.34,86.36 E23.U2 | v209.55,125.09 209.55,113.66 208.28,112.39 208.28,111.76 E24.K2
  Bottom 0.254: E25.D2 192.41,126.36 193.68,125.09 200.66,125.09 201.93,126.36 204.47,126.36 E24.D2 205.1,126.36 206.38,125.09 v209.55,125.09 211.46,125.09 212.09,125.73 216.53,125.73 217.17,126.36 E23.D2 217.81,126.36 222.25,126.36 223.52,125.09 224.16,125.09 224.79,125.73 229.24,125.73 229.87,126.36 E22.D2 | E25.K2 195.58,110.49 196.22,109.85 200.66,109.85 201.29,109.22 206.38,109.22 207.65,110.49 E24.K2 208.28,111.12 212.09,111.12 214,113.03 219.07,113.03 220.34,111.76 E23.K2 | E25.U2 195.58,85.09 196.22,84.45 200.66,84.45 201.29,83.82 204.47,83.82 205.74,85.09 207.65,85.09 E24.U2 208.28,86.36 208.91,86.99 213.36,86.99 214,87.63 214.63,87.63 215.9,86.36 220.34,86.36 E23.U2 | E25.N2 192.41,102.23 193.68,103.5 200.66,103.5 201.93,102.23 204.47,102.23 E24.N2 205.1,102.23 206.38,103.5 213.36,103.5 214.63,102.23 217.17,102.23 E23.N2
-WTB  (via drill 0.61)
  Top 0.254: B14.J2 332.11,316.87 332.11,313.06 333.38,311.79 333.38,306.07 334.64,304.8 334.64,302.26 B14.P2 | A13.M2 347.98,377.19 347.98,374.02 v350.52,371.48 349.25,370.21 349.25,353.06 347.98,351.79 347.98,341.63 349.25,340.36 349.25,299.09 347.98,297.81 347.98,295.91 B13.S2 | C13.R2 344.81,232.41 346.07,233.68 346.07,271.15 344.17,273.05 344.17,283.85 342.26,285.75 342.26,287.66 342.9,288.29 v342.9,292.1 342.9,296.55 v341,298.45 | A37.R2 40.01,367.67 40.01,367.03 41.27,365.76 41.27,246.38 40.01,245.11 C37.L2 40.01,243.84 40.01,241.94 44.45,237.49 44.45,206.38 v45.72,205.1 | v123.83,204.47 123.83,167.64 119.38,163.19 119.38,159.38 D31.S2 | v227.33,215.9 226.06,214.63 v226.06,211.45
  Route2 0.254: v306.7,227.33 313.06,227.33 313.69,226.69 322.58,226.69 326.39,230.5 328.93,230.5 329.56,229.87 338.45,229.87 339.09,230.5 343.54,230.5 344.17,231.14 C13.R2 | v290.19,224.16 280.67,214.63 228.6,214.63 v227.33,215.9 | v226.06,211.45 224.79,212.72 222.25,212.72 220.98,211.45 205.74,211.45 203.84,213.36 178.44,213.36 173.35,208.28 132.72,208.28 129.54,205.1 124.46,205.1 v123.83,204.47
  Bottom 0.254: v350.52,371.48 349.25,370.21 346.07,370.21 344.81,368.94 A13.R2 | v342.9,292.1 342.9,294.64 347.35,294.64 B13.S2 | v341,298.45 339.09,300.36 335.92,300.36 335.28,300.99 B14.P2 | v123.83,204.47 113.67,204.47 113.03,205.1 v45.72,205.1 | v306.7,227.33 307.98,226.06 307.98,224.16 304.8,224.16 304.17,224.79 301.62,224.79 300.36,223.52 291.46,223.52 290.83,224.16 v290.19,224.16
-WTD  (via drill 0.61)
  Top 0.254: v161.93,189.86 161.93,210.82 v161.29,211.45 | v206.38,213.36 206.38,195.58 v208.28,193.67 | v344.81,252.73 344.81,256.54 C13.F2 | v352.43,330.84 352.43,340.36 353.06,341 353.06,357.5 352.43,358.14 352.43,372.11 358.77,378.46 358.77,398.15 357.5,399.42 A12.D2
  Route2 0.254: v161.93,189.86 163.19,188.59 163.19,187.32 161.29,185.42 160.02,185.42 158.12,187.32 157.48,187.32 155.57,185.42 152.4,185.42 152.4,170.81 145.41,163.83 144.78,163.83 144.78,159.38 D29.S2 | v208.28,193.67 210.19,195.58 213.36,195.58 214,194.94 222.88,194.94 223.52,195.58 226.06,195.58 226.69,194.94 235.59,194.94 242.57,201.93 251.46,201.93 252.09,201.29 260.99,201.29 261.62,201.93 264.16,201.93 264.8,201.29 265.43,201.29 v267.97,203.84 | v318.77,220.98 321.31,223.52 326.39,223.52 328.3,225.42 329.56,225.42 330.83,224.16 334.64,224.16 337.82,227.33 340.36,227.33 341,226.69 341.63,226.69 349.25,234.31 349.25,242.57 347.98,242.57 346.07,244.47 346.07,246.38 | 346.07,246.38 346.07,252.09 345.44,252.09 v344.81,252.73 | v369.57,234.31 361.31,242.57 354.96,242.57 351.15,246.38 346.07,246.38
  Route3 0.254: v267.97,203.84 278.13,214 v278.13,218.44 | v382.27,234.31 382.27,232.41 C10.R2 | v352.43,330.84 358.77,324.49 358.77,313.69 363.22,309.25 365.12,309.25 365.12,288.29 372.75,280.67 372.75,274.96 365.12,267.34 365.12,262.25 v363.22,260.35
  Bottom 0.254: v161.29,211.45 163.19,213.36 174.62,213.36 175.26,214 205.74,214 v206.38,213.36 | v278.13,218.44 278.76,217.81 283.85,217.81 287.02,220.98 288.29,220.98 291.46,217.81 294.64,217.81 295.91,219.07 297.81,219.07 299.72,217.17 314.32,217.17 318.13,220.98 v318.77,220.98 | v382.27,234.31 379.73,236.85 377.19,236.85 374.01,233.68 370.2,233.68 v369.57,234.31 | v363.22,260.35 361.95,259.08 354.96,259.08 354.33,258.44 351.79,258.44 351.15,259.08 346.07,259.08 344.81,257.81 C13.F2
-WTE  (via drill 0.61)
  Top 0.254: v349.25,280.04 v349.25,219.71 349.25,145.41 v351.15,143.51 | v336.55,280.04 336.55,296.55 | 336.55,296.55 333.38,299.72 332.11,299.72 332.11,299.09 B14.R2 | v476.25,73.66 476.25,21.59 472.44,17.78 472.44,13.97 471.81,13.34 F03.V2 | v377.82,78.1 377.82,137.16 376.56,138.43 v376.56,142.24 | 336.55,296.55 336.55,318.77 335.28,320.04 B14.H2 | v317.5,320.68 317.5,328.3 318.77,329.56 B15.D2
  Bottom 0.254: v349.25,219.71 348.62,220.34 342.9,220.34 342.9,223.52 344.17,224.79 C13.T2 | v349.25,280.04 v336.55,280.04 | v476.25,73.66 428.62,73.66 426.72,75.56 408.94,75.56 408.31,76.2 401.95,76.2 399.42,78.74 378.46,78.74 v377.82,78.1 | v376.56,142.24 352.43,142.24 v351.15,143.51 | v317.5,320.68 318.77,319.41 327.66,319.41 328.3,318.77 333.38,318.77 334.64,320.04 B14.H2
-WTF  (via drill 0.61)
  Top 0.254: A14.D2 332.11,399.42 333.38,398.15 333.38,386.08 334.64,384.81 A14.K2 334.64,383.54 333.38,382.27 333.38,346.08 336.55,342.9 | 342.9,328.3 342.9,300.36 344.17,299.09 B13.R2 | 342.9,328.3 344.17,329.56 B13.D2 | 336.55,342.9 337.82,341.63 344.81,341.63 344.81,339.09 342.9,337.19 342.9,328.3 | v352.43,264.8 352.43,276.86 350.52,278.77 350.52,283.85 349.25,285.12 v349.25,297.81 | v147.96,235.59 146.05,233.68 146.05,154.31 144.78,153.03 D29.U2 | v150.5,238.12 152.4,240.03 152.4,313.06 | 152.4,313.06 152.4,330.84 153.03,331.47 156.84,331.47 156.84,327.66 B28.E2 | v154.31,313.06 152.4,313.06 | 336.55,342.9 337.82,344.17 v337.82,351.16 | v248.92,351.79 248.28,351.16 248.28,337.82 247.65,337.19 v247.65,312.42
  Route2 0.254: v150.5,238.12 v147.96,235.59 | v337.82,351.16 335.92,349.25 290.19,349.25 v288.29,351.16
  Bottom 0.254: C08.D2 407.67,263.53 403.86,263.53 401.95,265.43 396.88,265.43 395.61,264.16 C09.D2 394.97,263.53 391.8,263.53 389.89,265.43 388.62,265.43 387.99,264.8 379.1,264.8 378.46,265.43 375.92,265.43 375.29,264.8 366.39,264.8 365.76,265.43 358.77,265.43 357.5,264.16 C12.D2 356.87,264.16 356.24,264.8 v352.43,264.8 | v349.25,297.81 344.81,297.81 B13.R2 | v154.31,313.06 160.66,313.06 161.29,312.42 163.83,312.42 164.47,313.06 173.35,313.06 173.99,312.42 176.53,312.42 177.16,313.06 186.06,313.06 186.69,312.42 189.23,312.42 189.87,313.06 198.75,313.06 199.39,312.42 201.93,312.42 202.56,313.06 211.46,313.06 212.09,312.42 214.63,312.42 215.26,313.06 224.16,313.06 224.79,312.42 229.24,312.42 229.87,311.79 B22.L2 230.5,311.79 231.78,313.06 236.85,313.06 237.49,312.42 v247.65,312.42 | v288.29,351.16 271.78,351.16 271.14,351.79 v248.92,351.79
-WTI  (via drill 0.61)
  Top 0.254: 336.55,367.03 335.28,365.76 A14.S2 | 336.55,377.83 336.55,394.97 335.28,396.24 A14.E2 | 336.55,367.03 336.55,377.83 | 336.55,377.83 v338.45,377.83 | v384.81,227.33 384.18,227.97 384.18,260.99 382.9,262.25 382.9,262.89 C10.D2 | 336.55,367.03 339.73,363.86 v339.73,344.17
  Route3 0.254: v366.39,345.44 371.48,340.36 371.48,324.49 374.65,321.31 374.65,320.68 375.92,319.41 378.46,319.41 379.1,318.77 384.18,318.77 384.18,308.61 382.9,307.34 382.9,306.71 384.18,305.44 384.18,280.67 382.9,279.4 382.9,271.78 384.18,270.51 384.18,268.61 382.9,267.34 382.9,264.16 C10.D2
  Bottom 0.254: v338.45,377.83 337.82,377.83 336.55,376.56 332.11,376.56 332.11,380.37 A14.L2 | v384.81,227.33 389.25,227.33 389.89,226.69 394.33,226.69 394.97,226.06 C09.T2 | v339.73,344.17 365.12,344.17 v366.39,345.44
-WTMEM_C/W  (via drill 0.61)
  Top 0.254: v25.4,92.07 25.4,59.69 22.23,56.52 22.23,16.51 17.78,16.51 F39.U2 | v40.64,98.42 41.27,99.06 41.27,119.38 | 41.27,119.38 v41.27,123.19 | v12.7,143.51 12.7,168.91 13.34,169.54 13.34,173.35 13.97,173.99 D39.L2 | 41.27,119.38 v40.64,119.38
  Bottom 0.254: v25.4,92.07 26.67,93.34 35.56,93.34 v40.64,98.42 | v41.27,123.19 41.27,125.09 46.99,125.09 48.26,126.36 52.07,126.36 E36.D2 | v12.7,143.51 12.7,134.62 15.24,134.62 21.59,128.27 23.5,128.27 29.21,122.55 35.56,122.55 38.73,119.38 v40.64,119.38
-WTMEM_R/W  (via drill 0.61)
  Top 0.254: v73.03,113.03 73.03,88.27 68.58,83.82 68.58,81.91 69.85,80.64 69.85,51.44 50.8,32.38 50.8,6.98 55.24,2.54 55.24,1.27 47.62,1.27 33.66,15.24 30.48,15.24 F38.U2 | v60.33,116.84 v60.33,177.8 60.33,252.09 v58.42,254
  Bottom 0.254: v73.03,113.03 72.39,112.39 62.87,112.39 59.05,116.2 | 59.05,116.2 53.98,116.2 52.7,114.93 E36.J2 | v60.33,177.8 55.88,177.8 D36.K2 | v60.33,116.84 59.69,116.2 59.05,116.2 | v58.42,254 57.15,252.73 54.61,252.73 48.26,259.08 40.01,259.08 40.01,262.89 C37.D2
-WTRD  (via drill 0.61)
  Top 0.254: v412.75,393.06 412.75,386.08 411.48,384.81 A08.K2 | v47.62,279.4 47.62,36.2 41.27,29.84 41.27,20.95 40.01,19.69 F37.T2 | v234.95,281.31 234.95,324.49 236.22,325.75 236.22,328.3 234.95,329.56 v234.95,347.98 | v280.67,346.71 282.57,348.62 282.57,369.57 281.31,370.84 281.31,374.02 A18.N2
  Route3 0.254: A08.K2 410.85,383.54 409.57,382.27 409.57,376.56 408.31,375.29 A08.N2
  Bottom 0.254: v412.75,393.06 408.31,393.06 A08.F2 | F38.T2 27.3,18.41 28.57,17.14 35.56,17.14 36.83,18.41 39.37,18.41 F37.T2 | A18.N2 281.31,375.29 281.94,375.92 286.38,375.92 287.02,376.56 289.56,376.56 290.19,375.92 299.08,375.92 302.89,379.73 311.79,379.73 315.6,375.92 324.49,375.92 325.12,376.56 327.66,376.56 328.3,375.92 337.19,375.92 337.82,376.56 340.36,376.56 341,375.92 349.88,375.92 350.52,376.56 353.06,376.56 353.69,375.92 362.58,375.92 363.22,376.56 365.76,376.56 366.39,375.92 375.29,375.92 379.1,379.73 387.99,379.73 391.8,375.92 400.69,375.92 401.32,376.56 401.95,376.56 403.23,375.29 407.67,375.29 A08.N2 | v47.62,279.4 48.26,280.04 58.42,280.04 59.05,280.67 160.66,280.67 161.29,281.31 198.12,281.31 199.39,280.04 205.74,280.04 206.38,280.67 209.55,280.67 210.82,281.94 234.31,281.94 v234.95,281.31 | v234.95,347.98 250.19,347.98 252.73,345.44 262.89,345.44 263.52,346.08 280.04,346.08 v280.67,346.71
-WTS  (via drill 0.61)
  Top 0.254: v392.43,154.31 393.06,154.94 393.06,157.48 393.7,158.11 v393.7,174.62 | v403.23,176.53 403.23,186.06 404.5,187.32 v404.5,188.59 | v306.07,327.66 306.07,329.56 B16.D2 | v379.1,231.78 381,233.68 381,249.56 v379.73,250.82
  Route2 0.254: v388.62,104.77 384.18,100.33 379.1,100.33 375.29,96.52 368.94,96.52 365.76,93.34 361.31,93.34 360.68,92.71 E12.S2 | 304.17,325.75 303.53,325.12 300.99,325.12 300.36,325.75 297.81,325.75 v296.55,324.49 | 304.17,325.75 v306.07,327.66 | v293.37,319.41 289.56,315.6 283.21,315.6 v281.31,313.69 | v244.47,291.47 243.84,290.83 237.49,290.83 233.68,287.02 224.79,287.02 220.98,290.83 214.63,290.83 211.46,294 210.19,294 208.28,292.1 205.1,295.28 203.84,295.28 198.75,290.2 196.22,290.2 v195.58,290.83 | v175.9,292.74 170.18,287.02 161.29,287.02 160.66,287.66 151.76,287.66 151.13,287.02 148.59,287.02 147.96,287.66 139.06,287.66 135.25,283.85 134.62,283.85 132.08,286.39 131.44,286.39 128.91,283.85 119.38,283.85 v118.11,285.12 | v375.92,260.35 371.48,264.8 365.12,264.8 v360.68,269.24 | v361.31,286.39 360.68,287.02 351.79,287.02 351.15,287.66 344.81,287.66 v344.17,288.29 | v334.64,323.22 332.74,325.12 326.39,325.12 325.75,325.75 323.85,325.75 321.94,323.85 321.31,323.85 320.04,325.12 313.69,325.12 313.06,325.75 304.17,325.75
  Route3 0.254: v388.62,104.77 390.52,106.68 390.52,125.09 393.7,128.27 393.7,153.03 v392.43,154.31 | v296.55,324.49 293.37,321.31 v293.37,319.41 | v281.31,313.69 279.4,311.79 279.4,299.72 v271.14,291.47 | v379.73,193.67 377.82,195.58 377.82,230.5 v379.1,231.78 | v379.73,250.82 377.82,252.73 377.82,258.44 v375.92,260.35 | v360.68,269.24 358.77,271.15 358.77,278.77 361.31,281.31 v361.31,286.39 | v344.17,288.29 338.45,294 336.55,294 336.55,321.31 v334.64,323.22
  Bottom 0.254: v393.7,174.62 393.7,176.53 v403.23,176.53 | D06.D2 433.07,193.04 429.26,193.04 427.99,191.77 426.72,191.77 426.08,192.41 417.19,192.41 413.38,188.59 v404.5,188.59 400.69,192.41 389.89,192.41 389.25,191.77 381.63,191.77 v379.73,193.67 | 111.12,290.83 111.12,290.2 100.97,290.2 100.33,290.83 97.79,290.83 97.16,290.2 88.27,290.2 87.63,290.83 85.09,290.83 84.45,290.2 75.56,290.2 74.93,290.83 72.39,290.83 71.75,290.2 64.14,290.2 54.61,299.72 46.99,299.72 43.18,303.53 36.83,303.53 33.66,306.71 24.77,306.71 24.13,306.07 21.59,306.07 17.78,309.88 8.89,309.88 8.26,309.25 3.17,309.25 1.91,310.52 B40.L2 | 111.12,290.83 111.12,293.37 109.22,295.28 106.68,295.28 B32.S2 | v271.14,291.47 270.51,290.83 262.89,290.83 262.25,290.2 260.35,290.2 257.18,293.37 250.19,293.37 249.56,294 248.28,294 245.75,291.47 v244.47,291.47 | v195.58,290.83 189.23,290.83 186.06,294 177.16,294 v175.9,292.74 | v118.11,285.12 118.11,287.66 116.2,287.66 113.03,290.83 111.12,290.83
-WTWR  (via drill 0.61)
  Top 0.254: v36.83,20.32 39.37,22.86 39.37,24.77 F37.R2 | v372.11,195.58 368.3,199.39 368.3,206.38 v366.39,208.28 | v347.98,208.28 346.07,210.19 v346.07,232.41 | v340.36,233.04 337.19,236.22 337.19,236.85 336.55,237.49 v336.55,250.82 | v295.91,252.73 295.27,253.36 v295.27,262.89 v295.27,295.28 | v295.27,303.53 295.27,321.95 294,323.22 B17.F2 | v283.85,367.67 283.85,369.57 282.57,370.84 282.57,391.8 281.31,393.06 A18.F2 | v131.44,174.62 130.18,175.89 130.18,180.34 v132.08,182.25
  Route2 0.254: v117.47,154.94 130.18,167.64 130.18,174.62 v131.44,174.62 | v132.08,182.25 141.6,191.77 143.51,191.77 153.67,201.93 160.02,201.93 164.47,206.38 184.78,206.38 186.06,207.64 212.09,207.64 v212.72,207.01 | v233.04,262.25 233.68,261.62 238.76,261.62 239.4,262.25 248.28,262.25 248.92,261.62 251.46,261.62 255.27,265.43 264.16,265.43 264.8,264.8 273.69,264.8 274.32,265.43 276.86,265.43 277.5,264.8 286.38,264.8 287.02,265.43 288.29,265.43 290.83,262.89 292.1,262.89 292.74,262.25 294.64,262.25 v295.27,262.89
  Route3 0.254: v295.27,295.28 v295.27,303.53 | v283.85,367.67 279.4,363.22 279.4,356.24 276.86,353.7 276.86,344.17 279.4,341.63 279.4,330.84 278.13,329.56 278.13,328.93 v280.04,327.03 | v95.89,52.7 107.95,64.77 107.95,116.84 111.12,120.02 111.12,139.06 117.47,145.41 v117.47,154.94 | v212.72,207.01 213.36,207.64 213.36,212.72 215.9,215.26 215.9,233.04 228.6,245.75 228.6,252.73 231.78,255.91 231.78,260.99 v233.04,262.25
  Bottom 0.254: v36.83,20.32 36.2,20.32 35.56,20.95 26.67,20.95 22.86,17.14 15.88,17.14 14.61,18.41 F39.T2 | v372.11,195.58 376.56,195.58 381,191.13 385.44,191.13 D10.E2 | v366.39,208.28 365.76,208.91 348.62,208.91 v347.98,208.28 | v346.07,232.41 345.44,233.04 v340.36,233.04 | v336.55,250.82 335.28,252.09 326.39,252.09 325.75,252.73 316.87,252.73 316.23,252.09 313.69,252.09 313.06,252.73 306.7,252.73 306.07,252.09 300.99,252.09 300.36,252.73 v295.91,252.73 | v280.04,327.03 281.31,325.75 289.56,325.75 290.83,324.49 293.37,324.49 B17.F2 | v95.89,52.7 85.72,42.55 80.01,42.55 63.5,26.03 62.23,26.03 59.69,23.49 52.07,23.49 48.26,27.3 45.72,27.3 43.81,25.4 40.01,25.4 F37.R2
A1  (via drill 0.61)
  Route2 0.254: v381,231.14 381,224.16 378.46,224.16 v376.56,222.25 | v373.38,139.06 374.01,139.06 387.99,125.09 389.25,125.09 390.52,123.82 390.52,121.92 391.8,121.92 393.06,120.65 393.06,118.74 393.7,118.11 393.7,109.85 395.61,109.85 396.88,108.58 v396.88,104.77
  Route3 0.254: v381,231.14 381,270.51 382.27,271.78 382.27,277.5 381,278.77 381,290.2 382.27,291.47 B10.T2 | v376.56,222.25 375.29,220.98 375.29,220.34 374.65,219.71 374.65,194.31 371.48,191.13 371.48,170.81 372.75,169.54 372.75,167 371.48,165.73 371.48,146.69 374.65,143.51 374.65,140.97 373.38,139.7 v373.38,139.06
  Bottom 0.254: v396.88,104.77 396.88,99.06 398.14,99.06 E09.P2
A11(B)  (via drill 0.61)
  Top 0.254: v117.47,53.34 117.47,43.18 118.75,41.91 F31.K2
  Route2 0.254: v140.97,195.58 153.03,207.64 177.8,207.64 182.88,212.72 203.2,212.72 205.1,210.82 222.88,210.82 224.79,208.91 227.97,208.91 230.5,211.45 v231.14,211.45 | v262.25,320.68 262.89,321.31 263.52,321.31 265.43,323.22 267.97,323.22 B19.F2
  Route3 0.254: v117.47,53.34 117.47,120.02 123.83,126.36 123.83,151.76 v117.47,158.11 | v138.43,168.28 139.7,169.54 139.7,194.31 v140.97,195.58 | v231.14,211.45 234.95,215.26 234.95,220.34 238.12,223.52 238.12,230.5 239.4,231.78 239.4,233.04 238.12,234.31 238.12,250.19 241.3,253.36 241.3,273.69 v243.21,275.59 | v249.56,275.59 254.63,280.67 254.63,284.48 254,285.12 254,294.64 257.18,297.81 257.18,310.52 260.35,313.69 260.35,318.77 v262.25,320.68
  Bottom 0.254: v117.47,158.11 117.47,160.02 123.19,160.02 127,163.83 133.99,163.83 v138.43,168.28 | v243.21,275.59 v249.56,275.59
A12(B)  (via drill 0.61)
  Top 0.254: v120.65,74.93 120.65,36.83 119.38,35.56 F31.M2 | v174.62,75.56 174.62,203.84 175.9,205.1 v175.9,212.09 | v234.95,209.55 234.95,266.06 238.12,269.24 238.12,274.32 240.66,276.86 240.66,287.66 241.3,288.29 v241.3,303.53 | v232.41,302.9 231.78,303.53 231.78,321.95 | 231.78,321.95 230.5,323.22 B22.F2 | 231.78,321.95 231.78,354.33 238.12,360.68 238.12,366.4 241.3,369.57 241.3,385.45 242.57,386.72 A21.J2
  Bottom 0.254: v120.65,74.93 121.28,75.56 v174.62,75.56 | v175.9,212.09 176.53,212.72 204.47,212.72 206.38,210.82 222.88,210.82 224.79,208.91 229.24,208.91 229.87,209.55 v234.95,209.55 | v241.3,303.53 237.49,303.53 236.85,302.9 v232.41,302.9
AC00  (via drill 0.61)
  Top 0.254: v464.82,177.8 466.73,175.89 v466.73,167.64 v466.73,159.38 | v409.57,6.98 409.57,23.49 408.31,24.77 F08.R2 | v462.28,82.55 460.38,80.64 460.38,52.7 461.64,51.44 461.64,48.26 F04.H2
  Route3 0.254: F04.H2 461.64,46.99 460.38,45.72 460.38,14.61 459.11,13.34 F04.V2 | v466.73,159.38 466.73,86.99 v462.28,82.55
  Bottom 0.254: v464.82,177.8 463.55,176.53 459.11,176.53 452.75,182.88 450.21,182.88 449.58,183.51 D05.H2 | v466.73,167.64 467.36,167 473.07,167 474.35,165.73 D03.P2 | v409.57,6.98 410.21,7.62 437.51,7.62 440.69,10.79 457.2,10.79 458.47,12.06 F04.V2
AC11B  (via drill 0.61)
  Top 0.254: A34.S2 80.64,365.76 80.01,366.4 80.01,370.21 79.38,370.84 79.38,398.15 78.11,399.42 A34.D2 | B25.L2 192.41,311.79 193.04,312.42 193.04,316.23 193.68,316.87 193.68,321.95 196.85,325.12 196.85,382.27 195.58,383.54 A25.K2 | v88.9,402.59 96.52,410.21 96.52,418.47 97.16,419.1 151.76,419.1 151.76,415.93 152.4,415.29 v152.4,380.37 | v473.71,341 475.62,341 476.25,340.36 476.25,328.93 474.98,327.66 B03.E2 | v403.86,341 403.23,341.63 v403.23,364.49 | v403.23,41.91 403.23,48.26 407.67,52.7 407.67,56.52 F08.D2 408.31,57.79 409.57,59.05 409.57,77.47 405.76,81.28 405.76,84.45 406.4,85.09 v406.4,102.23 | v422.27,180.34 v422.27,167 | v449.58,218.44 448.94,217.81 448.94,209.55 447.04,207.64 447.04,201.29 447.68,200.66 v447.68,192.41 | v424.18,186.69 424.18,184.78 D07.H2
  Route3 0.254: v406.4,102.23 406.4,139.06 412.75,145.41 412.75,163.19 411.48,164.47 D08.P2 | v468.63,226.69 469.9,227.97 469.9,273.69 468.63,274.96 468.63,285.12 473.07,289.56 473.07,325.12 474.35,326.39 B03.E2 | v332.11,390.53 v325.75,384.18 | v379.1,394.34 393.7,379.73 393.7,370.21 394.97,368.94 A09.R2
  Bottom 0.254: v88.9,402.59 87.63,401.32 87,401.32 86.36,401.96 79.38,401.96 78.11,400.69 A34.D2 | v152.4,380.37 153.67,379.1 162.56,379.1 163.19,379.73 168.28,379.73 169.54,378.46 A27.M2 170.18,378.46 170.81,379.1 175.26,379.1 175.9,379.73 180.34,379.73 180.97,379.1 187.96,379.1 192.41,383.54 194.94,383.54 A25.K2 195.58,383.54 196.22,382.91 200.66,382.91 201.29,382.27 210.19,382.27 210.82,382.91 213.36,382.91 214,382.27 222.88,382.27 223.52,382.91 226.06,382.91 226.69,382.27 235.59,382.27 236.22,382.91 238.76,382.91 239.4,382.27 248.28,382.27 248.92,382.91 251.46,382.91 252.09,382.27 260.99,382.27 261.62,382.91 264.16,382.91 264.8,382.27 273.69,382.27 277.5,386.08 286.38,386.08 290.19,382.27 299.08,382.27 299.72,382.91 302.26,382.91 302.89,382.27 311.79,382.27 312.42,382.91 314.96,382.91 315.6,382.27 323.85,382.27 v325.75,384.18 | v473.71,341 469.26,341 468.63,341.63 404.5,341.63 v403.86,341 | v403.23,364.49 400.05,367.67 395.61,367.67 A09.R2 | v403.23,41.91 398.78,41.91 F09.K2 | v422.27,167 417.19,167 415.93,165.73 411.48,165.73 D08.P2 | v422.27,180.34 422.27,183.51 423.55,183.51 D07.H2 | v468.63,226.69 465.45,223.52 459.74,223.52 456.56,220.34 453.39,220.34 452.75,220.98 452.12,220.98 v449.58,218.44 | v447.68,192.41 440.69,192.41 440.06,191.77 431.17,191.77 430.53,192.41 429.89,192.41 v424.18,186.69 | v332.11,390.53 333.38,391.8 340.36,391.8 344.17,395.61 353.06,395.61 353.69,394.97 362.58,394.97 363.22,395.61 365.76,395.61 366.39,394.97 375.29,394.97 375.92,395.61 377.82,395.61 v379.1,394.34
AM  (via drill 0.61)
  Top 0.254: v222.25,113.03 222.25,104.14 221.62,103.5 221.62,99.69 220.98,99.06 E23.P2
  Bottom 0.254: v222.25,113.03 220.98,114.3 217.81,114.3 E23.J2
AND  (via drill 0.61)
  Top 0.254: v478.15,165.1 476.25,167 476.25,182.25 479.43,185.42 v479.43,193.67 | v151.13,155.57 149.22,157.48 149.22,205.74 151.13,207.64 v151.13,211.45 | v381.63,211.45 384.18,214 v384.18,217.81
  Route2 0.254: v493.39,205.74 493.39,215.9 495.3,217.81 495.3,255.91 v494.03,255.91 | v217.17,111.76 194.31,134.62 187.96,134.62 175.26,147.32 172.09,147.32 165.1,154.31 161.29,154.31 160.66,153.67 153.03,153.67 v151.13,155.57 | v387.99,217.81 v384.18,217.81 | v397.51,201.93 403.86,201.93 407.67,198.12 416.56,198.12 420.37,201.93 429.26,201.93 429.89,201.29 438.79,201.29 442.6,205.1 453.39,205.1 454.02,205.74 468,205.74 479.43,194.31 v479.43,193.67
  Route3 0.254: v464.82,28.58 476.25,40.01 476.25,72.39 473.07,75.56 473.07,132.72 476.25,135.89 476.25,158.11 479.43,161.29 479.43,163.83 v478.15,165.1 | v490.22,275.59 488.95,276.86 488.95,365.76 472.44,382.27 467.36,382.27 461.01,388.62 453.39,388.62 447.04,394.97 441.32,394.97 441.32,393.06 439.42,391.16 436.88,391.16 A06.H2 | v234.31,101.6 244.47,91.44 244.47,83.82 248.92,79.38 248.92,66.67 254,61.59 254,59.05 255.27,57.79 F20.D2 | v387.99,217.81 386.71,216.53 386.71,206.38 391.8,201.29 397.51,201.29 v397.51,201.93
  Bottom 0.254: v464.82,28.58 463.55,29.84 459.74,29.84 453.39,23.49 447.04,23.49 438.15,14.61 433.7,14.61 433.7,18.41 F06.T2 | v479.43,193.67 480.69,194.94 482.6,194.94 v493.39,205.74 | v494.03,255.91 491.49,258.44 491.49,262.25 492.12,262.89 492.12,275.59 v490.22,275.59 | v234.31,101.6 226.06,109.85 219.07,109.85 v217.17,111.76 | v151.13,211.45 153.67,214 173.99,214 174.62,214.63 210.19,214.63 212.72,212.09 222.88,212.09 223.52,212.72 316.23,212.72 316.87,212.09 333.38,212.09 334.01,211.45 v381.63,211.45
AND+TAD+DCA+IAC+CMA+ROTL+OP2  (via drill 0.61)
  Route3 0.254: v211.46,300.36 208.28,303.53 208.28,307.34 B24.M2
  Bottom 0.254: B20.P2 258.44,302.26 256.54,304.17 255.91,304.17 B20.N2 255.27,304.17 252.73,304.17 248.28,299.72 239.4,299.72 238.76,300.36 236.22,300.36 235.59,299.72 226.69,299.72 226.06,300.36 223.52,300.36 222.88,299.72 212.09,299.72 v211.46,300.36
AND+TAD+ISZ  (via drill 0.61)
